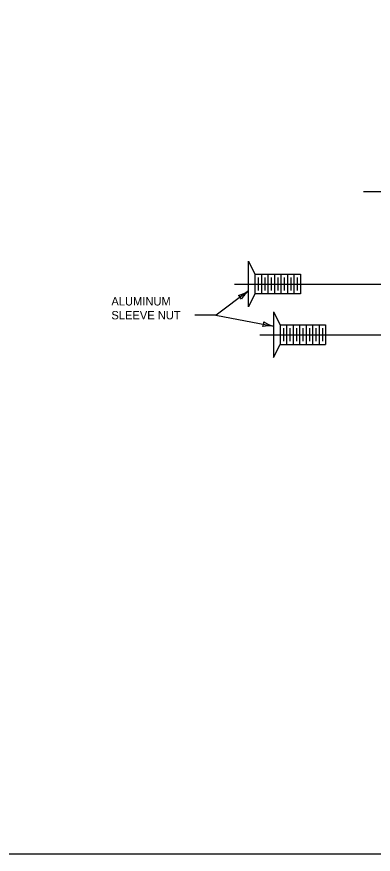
# Model space of a CAD drawing. Extents: x 49991.4 to 50021, y 49987.6 to 50011.4.
# Drawn here: x 50009.11 to 50011.68, y 49987.8 to 49993.84 of the extents above; entities that cross this region are included whole.
import ezdxf

# ---------------------------------------------------------------- set-up
doc = ezdxf.new("R2010")
doc.units = 0
for name, color, linetype in [('Level 1', 7, 'Continuous'), ('Level 2', 7, 'Continuous'), ('Level 3', 7, 'Continuous'), ('Level 5', 7, 'Continuous')]:
    doc.layers.add(name, color=color, linetype=linetype)

msp = doc.modelspace()

# ---------------------------------------------------------------- linework, layer by layer
at = {"layer": 'Level 1'}
for p, q in [((50010.7781, 49991.7475), (50010.7781, 49992.0757)), ((50010.7781, 49992.0757), (50010.825, 49991.9819)), ((50010.825, 49991.9819), (50010.825, 49991.8413)), ((50010.825, 49991.9819), (50011.1531, 49991.9819)), ((50010.8719, 49991.9819), (50010.8719, 49991.8413)), ((50010.9188, 49991.9819), (50010.9188, 49991.8413)), ((50010.9656, 49991.9819), (50010.9656, 49991.8413)), ((50011.0125, 49991.9819), (50011.0125, 49991.8413)), ((50011.0594, 49991.9819), (50011.0594, 49991.8413)), ((50011.1063, 49991.9819), (50011.1063, 49991.8413)), ((50011.1531, 49991.9819), (50011.1531, 49991.8413)), ((50010.8485, 49991.9585), (50010.8485, 49991.8648)), ((50010.8954, 49991.9585), (50010.8954, 49991.8648)), ((50010.9422, 49991.9585), (50010.9422, 49991.8648)), ((50010.9891, 49991.9585), (50010.9891, 49991.8648)), ((50011.036, 49991.9585), (50011.036, 49991.8648)), ((50011.0829, 49991.9585), (50011.0829, 49991.8648)), ((50011.1297, 49991.9585), (50011.1297, 49991.8648)), ((50010.825, 49991.8413), (50010.7781, 49991.7475)), ((50011.1531, 49991.8413), (50010.825, 49991.8413)), ((50010.9598, 49991.7099), (50010.9598, 49991.3818)), ((50010.9598, 49991.7099), (50011.0067, 49991.6162)), ((50011.0067, 49991.6162), (50011.3348, 49991.6162)), ((50011.0067, 49991.6162), (50011.0067, 49991.4755)), ((50011.0535, 49991.6162), (50011.0535, 49991.4755)), ((50011.1004, 49991.6162), (50011.1004, 49991.4755)), ((50011.1473, 49991.6162), (50011.1473, 49991.4755)), ((50011.1942, 49991.6162), (50011.1942, 49991.4755)), ((50011.241, 49991.6162), (50011.241, 49991.4755)), ((50011.2879, 49991.6162), (50011.2879, 49991.4755)), ((50011.3348, 49991.6162), (50011.3348, 49991.4755)), ((50011.0301, 49991.5928), (50011.0301, 49991.499)), ((50011.077, 49991.5928), (50011.077, 49991.499)), ((50011.1239, 49991.5928), (50011.1239, 49991.499)), ((50011.1708, 49991.5928), (50011.1708, 49991.499)), ((50011.2176, 49991.5928), (50011.2176, 49991.499)), ((50011.2645, 49991.5928), (50011.2645, 49991.499)), ((50011.3114, 49991.5928), (50011.3114, 49991.499)), ((50010.9598, 49991.3818), (50011.0067, 49991.4755)), ((50011.0067, 49991.4755), (50011.3348, 49991.4755))]:
    msp.add_line(p, q, dxfattribs=at)
msp.add_lwpolyline([(49999.3835, 49998.9992), (50016.7501, 49998.9992), (50016.7501, 49987.7988), (49999.3835, 49987.7988)], close=True, dxfattribs=at)
at = {"layer": 'Level 3'}
for p, q in [((50010.7781, 49991.8619), (50010.545, 49991.6869)), ((50010.545, 49991.6869), (50010.3914, 49991.6869)), ((50010.5442, 49991.6865), (50010.9598, 49991.6078))]:
    msp.add_line(p, q, dxfattribs=at)
for centre, radius, start, end in [((50010.6521, 49992.0451), 0.2223, 284.34776, 304.53127), ((50010.927, 49991.6827), 0.233, 129.71906, 148.96891), ((50010.6756, 49991.7849), 0.0548, 19.03057, 54.75293), ((50010.8338, 49991.6317), 0.0548, 331.41652, 7.13888), ((50011.0101, 49991.8244), 0.2223, 236.73371, 256.91722), ((50010.9278, 49991.377), 0.233, 82.10501, 101.35486)]:
    msp.add_arc(centre, radius, start, end, dxfattribs=at)
at = {"layer": 'Level 5'}
for p, q in [((50011.6071, 49992.5796), (50014.1123, 49992.5796)), ((50010.6781, 49991.9116), (50011.2893, 49991.9116)), ((50011.2893, 49991.9116), (50014.0869, 49991.9116)), ((50010.8598, 49991.5459), (50011.4709, 49991.5459)), ((50011.4709, 49991.5459), (50012.6672, 49991.5459))]:
    msp.add_line(p, q, dxfattribs=at)

# ---------------------------------------------------------------- texts
at = {"layer": 'Level 2'}
for s, p in [('ALUMINUM', (50009.7901, 49991.7569)), ('SLEEVE NUT', (50009.7901, 49991.6569))]:
    msp.add_text(s, height=0.06, dxfattribs=at).set_placement(p)

doc.saveas('drawing.dxf')
